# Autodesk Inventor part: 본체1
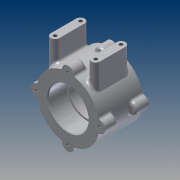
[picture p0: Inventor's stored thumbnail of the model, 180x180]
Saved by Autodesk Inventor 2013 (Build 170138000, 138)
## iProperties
Created: 2015-03
Part Number: 본체1
Material: 알루미늄 6061
Document SubType Name: Modeling
Designer: cad8
Density: 2.40731 g/cm^3
Mass: 400.764 g
Surface Area: 332.93 cm^2
Volume: 166.478 cm^3
Author: cad8
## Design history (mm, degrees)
sketch "스케치1"
  geometry: C1 r 37 at (0, 0); 1 further point
  constraints: 1 centre point, 1 coincident
  dimensions: "d0" = 74 diameter of C1
extrude "돌출1" new body sketch "스케치1" distance "d2" = 52; taper "d3" = 0 deg
sketch "스케치2" dims "d4" = 74
  geometry: L1 (0, 2.614)-(0, 37); C1 r 37 at (0, 0) reference; C2 r 7 at (0, 37); 1 further point
  constraints: 2 coincident, 2 end point, 1 centre point, 1 vertical, 1 vertical alignment, 2 other
  dimensions: "d6" = 14 diameter of C2
extrude "돌출2" join sketch "스케치2" distance "d7" = 15; taper "d8" = 0 deg
sketch "스케치3"
  geometry: A1 r 7 centre (0, 37) between (6.969, 36.338) and (-6.969, 36.338) reference; 1 further point
  constraints: 1 coincident
hole "구멍1" sketch "스케치3" at (0, 37) diameter "d9" = 3.242; stored, may be unused: countersink angle "d13" = 90 deg, drill point angle "d15" = 118 deg; dims "d10" = 8, "d11" = 4, "d12" = 2, "d14" = 11
node "작업 평면1"
node "작업 평면2"
sketch "스케치4"
  geometry: L1 (-37, 15)-(-37, 37) reference; L2 (37, 15)-(37, 37) reference; L3 (36.338, 52)-(36.338, 37) reference; L4 (36.338, 37)-(36.338, 37) reference; L5 (36.338, 37)-(36.338, 52) reference; L6 (6.969, 52)-(36.338, 52) reference; L7 (6.969, 52)-(6.969, 37) reference; L8 (6.969, 37)-(-6.969, 37) reference; L9 (-6.969, 37)-(-6.969, 52) reference; L10 (-36.338, 52)-(-6.969, 52) reference; L11 (-36.338, 52)-(-36.338, 37) reference; L12 (-36.338, 37)-(-36.338, 37) reference; L13 (-36.338, 37)-(-36.338, 52) reference; L14 (-6.969, 52)-(-36.338, 52) reference; L15 (-6.969, 52)-(-6.969, 37) reference; L16 (-6.969, 37)-(6.969, 37) reference; L17 (6.969, 37)-(6.969, 52) reference; L18 (36.338, 52)-(6.969, 52) reference; L19 (36.338, 0)-(36.338, 15) reference; L20 (36.338, 15)-(36.338, 15) reference; L21 (36.338, 15)-(36.338, 0) reference; L22 (6.969, 0)-(36.338, 0) reference; L23 (6.969, 0)-(6.969, 15) reference; L24 (6.969, 15)-(-6.969, 15) reference; L25 (-6.969, 15)-(-6.969, 0) reference; L26 (-36.338, 0)-(-6.969, 0) reference; L27 (-36.338, 0)-(-36.338, 15) reference; L28 (-36.338, 15)-(-36.338, 15) reference; L29 (-36.338, 15)-(-36.338, 0) reference; L30 (-6.969, 0)-(-36.338, 0) reference; L31 (-6.969, 0)-(-6.969, 15) reference; L32 (-6.969, 15)-(6.969, 15) reference; L33 (6.969, 15)-(6.969, 0) reference; L34 (36.338, 0)-(6.969, 0) reference; L35 (-6.969, 52)-(-6.969, 37) reference; L36 (-6.969, 52)-(6.969, 52) reference; L37 (6.969, 37)-(6.969, 52) reference; L38 (-6.969, 37)-(6.969, 37) reference; L39 (-6.969, 15)-(-6.969, 0) reference; L40 (-6.969, 15)-(6.969, 15) reference; L41 (6.969, 0)-(6.969, 15) reference; L42 (-6.969, 0)-(6.969, 0) reference; L43 (-37, 26)-(3.417, 26); L44 (0, 0)-(0, 30.982); L45 (-31.294, 46)-(-21.294, 46); L46 (-21.294, 46)-(-21.294, 6); L47 (-21.294, 6)-(-31.294, 6); L48 (-31.294, 6)-(-31.294, 46); L49 (16.706, 46)-(26.706, 46); L50 (26.706, 46)-(26.706, 6); L51 (26.706, 6)-(16.706, 6); L52 (16.706, 6)-(16.706, 46); L53 (-26.294, 6)-(-26.294, 15); L54 (21.706, 6)-(21.706, 13.564); 2 further points
  constraints: 24 end point, 7 parallel, 5 midpoint, 3 perpendicular, 2 horizontal, 2 horizontal alignment, 1 other
  dimensions: "d20" = 10 distance of L45.start L45.end; "d22" = 10 distance of L49.start L49.end; "d23" = 48 distance between parallel lines of L54 L53; "d24" = 40 distance between parallel lines of L51 L49
extrude "돌출3" join sketch "스케치4" distance "d25" = 56; taper "d26" = 0 deg
node "작업 평면3"
sketch "스케치5"
  geometry: L1 (-21.294, 46)-(-31.294, 46) reference; L2 (-31.294, 46)-(-31.294, 6) reference; L3 (-31.294, 6)-(-21.294, 6) reference; L4 (-21.294, 6)-(-21.294, 46) reference; L5 (26.706, 46)-(16.706, 46) reference; L6 (16.706, 46)-(16.706, 6) reference; L7 (16.706, 6)-(26.706, 6) reference; L8 (26.706, 6)-(26.706, 46) reference; L9 (6.969, 52)-(6.969, 37) reference; L10 (6.969, 52)-(-6.969, 52) reference; L11 (-6.969, 37)-(-6.969, 52) reference; L12 (6.969, 37)-(-6.969, 37) reference; L13 (-21.294, 46)-(-21.294, 6) reference; L14 (-21.294, 6)-(-31.294, 6) reference; L15 (-31.294, 6)-(-31.294, 46) reference; L16 (-31.294, 46)-(-21.294, 46) reference; L17 (26.706, 46)-(26.706, 6) reference; L18 (26.706, 6)-(16.706, 6) reference; L19 (16.706, 6)-(16.706, 46) reference; L20 (16.706, 46)-(26.706, 46) reference; L21 (36.338, 52)-(36.338, 37) reference; L22 (36.338, 37)-(36.338, 37) reference; L23 (36.338, 37)-(36.338, 52) reference; L24 (6.969, 52)-(36.338, 52) reference; L25 (6.969, 52)-(6.969, 37) reference; L26 (6.969, 37)-(-6.969, 37) reference; L27 (-6.969, 37)-(-6.969, 52) reference; L28 (-36.338, 52)-(-6.969, 52) reference; L29 (-36.338, 52)-(-36.338, 37) reference; L30 (-36.338, 37)-(-36.338, 37) reference; L31 (-36.338, 37)-(-36.338, 52) reference; L32 (-6.969, 52)-(-36.338, 52) reference; L33 (-6.969, 52)-(-6.969, 37) reference; L34 (-6.969, 37)-(6.969, 37) reference; L35 (6.969, 37)-(6.969, 52) reference; L36 (36.338, 52)-(6.969, 52) reference; L37 (36.338, 0)-(36.338, 15) reference; L38 (36.338, 15)-(36.338, 15) reference; L39 (36.338, 15)-(36.338, 0) reference; L40 (6.969, 0)-(36.338, 0) reference; L41 (6.969, 0)-(6.969, 15) reference; L42 (6.969, 15)-(-6.969, 15) reference; L43 (-6.969, 15)-(-6.969, 0) reference; L44 (-36.338, 0)-(-6.969, 0) reference; L45 (-36.338, 0)-(-36.338, 15) reference; L46 (-36.338, 15)-(-36.338, 15) reference; L47 (-36.338, 15)-(-36.338, 0) reference; L48 (-6.969, 0)-(-36.338, 0) reference; L49 (-6.969, 0)-(-6.969, 15) reference; L50 (-6.969, 15)-(6.969, 15) reference; L51 (6.969, 15)-(6.969, 0) reference; L52 (36.338, 0)-(6.969, 0) reference; L53 (-37, 15)-(-37, 37) reference; L54 (-31.294, 26)-(-15.141, 26); L55 (0, 37)-(0, 36.039); L56 (0, 52)-(0, 42.132); L57 (-26.294, 46)-(-26.294, 43.607); 6 further points
  constraints: 8 end point, 5 midpoint, 3 vertical alignment, 2 perpendicular, 1 collinear, 1 horizontal alignment, 1 parallel
  dimensions: "d34" = 48 distance of point (21.706, 41) point (-26.294, 41); "d36" = 5 distance from line of L5 point (21.706, 41); "d37" = 5 distance from line of L1 point (-26.294, 41); "d74" = 5 distance from line of point (21.706, 11) L7
hole "구멍2" sketch "스케치5" at (-26.294, 41), (21.706, 41), (-26.294, 11), (21.706, 11) diameter "d40" = 4.134; stored, may be unused: countersink angle "d44" = 90 deg, drill point angle "d46" = 118 deg; dims "d41" = 6, "d42" = 4, "d43" = 2, "d45" = 8
sketch "스케치6"
  geometry: C1 r 23.5 at (0, 0); A1 r 37 centre (0, 0) between (6.969, -36.338) and (36.338, -6.969) reference
  constraints: 1 centre point, 1 coincident
  dimensions: "d47" = 47 diameter of C1
extrude "돌출4" cut sketch "스케치6" distance "d49" = 22; taper "d50" = 0 deg
sketch "스케치7"
  geometry: C1 r 23.5 at (0, 0); A1 r 37 centre (0, 0) between (6.969, -36.338) and (36.338, -6.969) reference
  constraints: 1 centre point, 1 coincident
  dimensions: "d51" = 47 diameter of C1
extrude "돌출5" cut sketch "스케치7" distance "d53" = 22; taper "d54" = 0 deg
sketch "스케치8"
  geometry: C1 r 23.5 at (0, 0) reference; C2 r 21 at (0, 0)
  constraints: 1 centre point, 1 coincident
  dimensions: "d55" = 42 diameter of C2
extrude "돌출6" cut sketch "스케치8" distance "d57" = 22; taper "d58" = 0 deg
fillet "모깎기1" dims "d59" = 5
fillet "모깎기2" dims "d60" = 0.3
fillet "모깎기3" dims "d61" = 3
fillet "모깎기4" dims "d62" = 3
chamfer "모따기1" distance "d63" = 1; stored, may be unused: second distance "d64" = 2, angle "d65" = 45 deg
chamfer "모따기2" distance "d66" = 1; stored, may be unused: second distance "d67" = 2, angle "d68" = 45 deg
node "작업 평면5"
  node "작업 평면4"
sketch "스케치9"
  geometry: L1 (0, -18.921)-(0, 18.921) reference; L2 (-30.3, 23.5)-(-30.3, -23.5) reference; L3 (-62.4, 0)-(10.4, 0) reference; 2 further points
  constraints: 1 other
  dimensions: "d77" = 0 distance from line of point (-26, 0) L3; "d78" = 26 distance from line of L1 point (-26, 0)
feature "엠보싱1" sketch "스케치9" dims "d2" = 52, "d3" = 0, "d72" = 0.5, "d73" = 0
node "솔리드1"
pattern_circular "원형 패턴1" dims angle "d17" = 360 deg
mirror "대칭1"
node "투영된 루프1"
node "투영된 루프2"
node "투영된 루프3"
node "투영된 루프4"
node "투영된 루프5"
node "투영된 루프6"
node "투영된 루프7"
node "작업축1"
other parameters: "d19" = 0, "d27" = 56, "d69" = 135 deg
